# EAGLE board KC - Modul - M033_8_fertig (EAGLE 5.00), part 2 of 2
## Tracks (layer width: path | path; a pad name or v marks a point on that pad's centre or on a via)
80H  (via drill 0.2 pad 0.7)
  Top 0.375: v46.99,58.42 v46.99,71.12 | IC10.3 IC10.12
  Bottom 0.375: IC18.1 12.07,48.26 12.07,58.42 v46.99,58.42 | v46.99,71.12 46.99,73.02 55.88,73.02 IC10.3
/A0  (via drill 0.2 pad 0.7)
  Top 0.375: IC2.11 59.69,35.56 IC5.9 | v50.8,35.56 IC7.1
  Bottom 0.375: v50.8,35.56 59.69,35.56 IC5.9
/A1  (via drill 0.2 pad 0.7)
  Top 0.375: v53.34,40.64 IC7.2 | IC1.11 93.98,34.29 IC4.9
  Bottom 0.375: v53.34,40.64 72.39,40.64 73.66,39.37 91.44,39.37 92.71,40.64 93.98,39.37 IC4.9
/A2
  Top 0.375: IC2.12 57.15,35.56 IC5.8 57.15,39.37 55.88,39.37 IC7.3
/A3  (via drill 0.2 pad 0.7)
  Top 0.375: v91.44,46.99 90.17,45.72 90.17,41.27 88.9,41.27 IC4.8 91.44,34.29 IC1.12
  Bottom 0.375: IC7.4 59.69,46.99 v91.44,46.99
/A4  (via drill 0.2 pad 0.7)
  Top 0.375: IC2.13 54.61,35.56 IC5.7 | v60.96,35.56 IC7.5
  Bottom 0.375: v60.96,35.56 60.96,34.61 57.15,34.61 IC2.13
/A5  (via drill 0.2 pad 0.7)
  Top 0.375: v86.36,40.64 IC4.7 | v63.5,43.18 IC7.6
  Top 0.4: IC4.7 88.9,34.29 IC1.13
  Bottom 0.375: v86.36,40.64 73.66,40.64 72.39,41.91 69.85,41.91 68.58,43.18 v63.5,43.18
/A6  (via drill 0.2 pad 0.7)
  Top 0.375: IC2.14 52.07,35.56 IC5.6 52.07,39.37 54.61,39.37 v54.61,41.91 | IC7.11 58.42,50.8 59.69,50.8 59.69,46.99 58.42,45.72 v58.42,41.91
  Bottom 0.375: v54.61,41.91 v58.42,41.91
/A8  (via drill 0.2 pad 0.7)
  Top 0.375: IC5.5 49.53,35.56 IC2.15 52.07,30.48 v62.23,30.48 | v34.29,62.23 IC8.5 | v95.25,30.48 95.25,64.77 96.52,66.04 v96.52,68.58 | v72.39,93.98 v72.39,69.85 | v40.64,74.93 v40.64,93.98
  Bottom 0.375: v34.29,62.23 27.62,62.23 27.62,63.5 19.05,63.5 19.05,69.53 34.29,69.53 IC9.5 | v62.23,30.48 64.45,30.48 64.45,32.07 68.9,32.07 68.9,30.48 v95.25,30.48 | v96.52,68.58 95.25,69.85 v72.39,69.85 | v40.64,93.98 v72.39,93.98
  Bottom 0.61: v40.64,74.93 39.37,73.66 34.29,73.66 IC9.5 | v40.64,93.98 v72.39,93.98
/A9  (via drill 0.2 pad 0.7)
  Top 0.375: v101.6,34.29 101.6,54.93 102.87,56.2 v102.87,72.39 | v64.77,74.93 64.77,88.58 62.23,88.58 v62.23,91.44 | v33.02,91.44 33.02,81.28 34.29,80.01 35.56,80.01 35.56,77.47 36.83,76.2 IC9.6 36.83,69.85 35.56,68.58 35.56,66.04 36.83,64.77 IC8.6
  Top 0.4: IC4.5 83.82,34.29 IC1.15
  Bottom 0.375: IC1.15 83.82,34.29 v101.6,34.29 | v102.87,72.39 86.36,72.39 86.36,73.66 82.55,73.66 82.55,74.93 v64.77,74.93 | v33.02,91.44 v62.23,91.44
  Bottom 0.61: v33.02,91.44 v62.23,91.44
/A10
  Top 0.375: IC2.16 46.99,35.56 IC5.4
/A11
  Bottom 0.375: IC1.16 81.28,35.24 78.74,35.24 IC4.4
/A12
  Top 0.375: IC2.17 44.45,35.56 IC5.3
/A13  (via drill 0.2 pad 0.7)
  Top 0.375: IC1.17 78.74,34.29 77.47,34.29 76.2,35.56 IC4.3 76.2,41.27 74.93,41.27 v74.93,49.53 | IC21.1 v50.8,62.23 | v66.04,62.23 67.31,60.96 67.31,57.15 68.58,55.88 v68.58,50.8
  Bottom 0.375: v50.8,62.23 v66.04,62.23 | v68.58,50.8 69.85,49.53 v74.93,49.53
/A14  (via drill 0.2 pad 0.7)
  Top 0.375: v38.1,34.29 38.1,39.69 41.91,39.69 IC5.2
  Bottom 0.375: IC2.18 44.45,34.29 v38.1,34.29
/A15
  Top 0.375: IC1.18 76.2,34.29 IC4.2
A0  (via drill 0.2 pad 0.7)
  Top 0.375: IC17.12 52.07,104.14 53.34,102.87 53.34,100.33 52.07,99.06 IC16.12 v52.07,83.82 | IC5.11 v62.23,83.82
  Bottom 0.375: v62.23,83.82 v52.07,83.82
  Bottom 0.61: v52.07,83.82 v62.23,83.82
A1  (via drill 0.2 pad 0.7)
  Top 0.375: v106.68,113.03 107.95,113.03 107.95,96.52 110.49,96.52 110.49,80.01 v111.76,78.74 | v50.8,114.3 50.8,111.76 49.53,110.49 IC17.11 49.53,104.14 50.8,102.87 50.8,100.33 49.53,99.06 IC16.11
  Bottom 0.254: 70.17,112.71 72.07,112.71 | 73.98,112.71 75.88,112.71 | 77.79,112.71 79.69,112.71 | 81.6,112.71 83.5,112.71 | 85.41,112.71 87.31,112.71 | 89.22,112.71 91.12,112.71 | 93.03,112.71 94.93,112.71 | 99.38,112.71 101.28,112.71 | 101.92,112.71 103.82,112.71
  Bottom 0.61: v111.76,78.74 111.76,44.45 IC4.11 | 70.17,112.71 66.36,112.71 66.36,114.3 v50.8,114.3 | 72.07,112.71 73.98,112.71 | 75.88,112.71 77.79,112.71 | 79.69,112.71 81.6,112.71 | 83.5,112.71 85.41,112.71 | 87.31,112.71 89.22,112.71 | 91.12,112.71 93.03,112.71 | 94.93,112.71 99.38,112.71 | 101.28,112.71 101.92,112.71 | 103.82,112.71 106.36,112.71 v106.68,113.03
A2  (via drill 0.2 pad 0.7)
  Top 0.375: IC17.10 46.99,104.14 48.26,102.87 48.26,100.33 46.99,99.06 IC16.10 46.99,73.66 45.72,73.66 v45.72,41.91
  Bottom 0.375: IC5.12 59.69,42.86 51.75,42.86 51.75,41.91 v45.72,41.91
A3  (via drill 0.2 pad 0.7)
  Top 0.375: v90.17,91.44 90.17,93.98 85.09,93.98 85.09,110.49 81.28,110.49 v81.28,118.11 | v45.72,118.11 45.72,115.57 44.45,114.3 IC17.9 44.45,104.14 45.72,102.87 45.72,100.33 44.45,99.06 IC16.9 | v107.95,91.44 107.95,80.01 110.49,77.47 v110.49,45.72
  Bottom 0.254: 79.06,117.79 80.96,117.79 | 73.98,117.79 75.88,117.79 | 69.22,117.79 70.8,117.79 | 90.49,91.76 92.39,91.76 | 93.03,91.76 94.93,91.76 | 95.57,91.76 97.47,91.76
  Bottom 0.375: 95.25,45.72 92.71,45.72 IC4.12
  Bottom 0.61: 80.96,117.79 v81.28,118.11 | 75.88,117.79 79.06,117.79 | 70.8,117.79 73.98,117.79 | 69.22,117.79 46.04,117.79 v45.72,118.11 | 95.25,45.72 v110.49,45.72 | v90.17,91.44 90.49,91.76 | 92.39,91.76 93.03,91.76 | 94.93,91.76 95.57,91.76 | 97.47,91.76 107.63,91.76 v107.95,91.44
A4  (via drill 0.2 pad 0.7)
  Top 0.375: IC17.8 41.91,104.14 43.18,102.87 43.18,100.33 41.91,99.06 IC16.8 41.91,74.93 43.18,73.66 v43.18,46.99 | v57.15,46.99 IC5.13
  Bottom 0.375: v43.18,46.99 v57.15,46.99
A5  (via drill 0.2 pad 0.7)
  Top 0.375: IC16.7 39.37,99.06 40.64,100.33 40.64,102.87 39.37,104.14 IC17.7 | IC4.13 88.9,53.34 83.82,53.34 83.82,57.15 81.28,57.15 v81.28,62.23 | v67.31,62.23 67.31,99.06 68.58,100.33 v68.58,104.14
  Bottom 0.375: v67.31,62.23 v81.28,62.23 | v68.58,104.14 39.37,104.14 IC17.7
  Bottom 0.61: v67.31,62.23 v81.28,62.23
A6  (via drill 0.2 pad 0.7)
  Top 0.375: v96.52,111.76 96.52,113.03 105.41,113.03 105.41,78.74 107.95,76.2 v107.95,46.99 | v36.83,111.76 IC17.6 36.83,104.14 38.1,102.87 38.1,100.33 36.83,99.06 IC16.6
  Bottom 0.254: 65.09,111.76 66.99,111.76
  Bottom 0.375: 99.06,46.99 92.71,46.99 91.44,45.72 54.61,45.72 IC5.14
  Bottom 0.61: v96.52,111.76 66.99,111.76 | 99.06,46.99 v107.95,46.99 | v36.83,111.76 65.09,111.76
A7  (via drill 0.2 pad 0.7)
  Top 0.375: IC16.5 34.29,99.06 35.56,100.33 35.56,102.87 34.29,104.14 IC17.5 | v86.36,52.07 IC4.14 | v38.1,69.85 v38.1,85.09 | v52.07,69.85 52.07,63.5 54.61,63.5 54.61,57.78 55.88,57.78 IC7.12
  Bottom 0.375: 73.66,52.07 73.66,54.61 55.88,54.61 IC7.12 | IC16.5 34.29,85.09 v38.1,85.09 | v38.1,69.85 v52.07,69.85
  Bottom 0.61: 73.66,52.07 v86.36,52.07
A8  (via drill 0.2 pad 0.7)
  Top 0.375: IC17.27 36.83,115.57 35.56,114.3 35.56,104.14 36.83,102.87 IC16.27 36.83,100.33 35.56,99.06 v35.56,81.28 | v52.07,60.96 IC5.15 | v21.59,60.96 21.59,64.77 20.32,66.04 v20.32,81.28
  Bottom 0.375: v52.07,60.96 50.8,60.96 49.53,62.23 38.1,62.23 38.1,60.96 v21.59,60.96 | v20.32,81.28 v35.56,81.28
  Bottom 0.61: v20.32,81.28 v35.56,81.28
A9  (via drill 0.2 pad 0.7)
  Top 0.375: IC16.26 39.37,102.87 38.1,104.14 38.1,114.3 v39.37,115.57 IC17.26 | v105.41,43.18 v105.41,72.39 | v95.25,86.36 v95.25,106.68 | v68.58,105.41 v68.58,115.57
  Bottom 0.375: IC4.15 83.82,43.18 v105.41,43.18 | 95.57,86.36 v95.25,86.36 | v68.58,115.57 v39.37,115.57
  Bottom 0.61: v39.37,115.57 v68.58,115.57 | v68.58,105.41 69.85,106.68 v95.25,106.68 | 95.57,86.36 105.41,86.36 v105.41,72.39
A10  (via drill 0.2 pad 0.7)
  Top 0.375: IC17.23 46.99,115.57 45.72,114.3 45.72,104.14 46.99,102.87 IC16.23 46.99,100.33 45.72,99.06 v45.72,80.01 | v5.08,45.72 5.08,78.74 v6.35,78.74
  Bottom 0.375: IC5.16 49.53,45.72 v5.08,45.72 | 21.59,80.01 v45.72,80.01
  Bottom 0.61: v6.35,78.74 17.46,78.74 17.46,80.01 21.59,80.01
A11  (via drill 0.2 pad 0.7)
  Top 0.375: IC17.25 41.91,115.57 40.64,114.3 40.64,104.14 41.91,102.87 IC16.25 41.91,100.33 40.64,99.06 v40.64,96.52 | IC4.16 81.28,52.07 73.66,52.07 v73.66,81.28 | v55.88,81.28 v55.88,96.52
  Bottom 0.375: v73.66,81.28 v55.88,81.28 | v55.88,96.52 v40.64,96.52
  Bottom 0.61: v40.64,96.52 v55.88,96.52 | v55.88,81.28 v73.66,81.28
A12  (via drill 0.2 pad 0.7)
  Top 0.375: IC17.4 31.75,104.14 33.02,102.87 33.02,100.33 31.75,99.06 IC16.4 31.75,81.28 33.02,80.01 33.02,57.78 35.56,57.78 v35.56,43.18
  Bottom 0.375: IC5.17 46.99,43.18 v35.56,43.18
A13  (via drill 0.2 pad 0.7)
  Top 0.375: IC21.4 58.42,57.78 59.69,57.78 v59.69,53.34 | v78.74,50.8 IC4.17
  Bottom 0.375: v59.69,53.34 68.58,53.34 69.85,52.07 71.12,52.07 72.39,50.8 v78.74,50.8
AB0  (via drill 0.2 pad 0.7)
  Top 0.375: v59.69,11.43 IC2.9
  Bottom 0.375: 67.31,4.45 PAD110.1 PAD81.1
  Bottom 0.61: v59.69,11.43 63.5,11.43 67.31,7.62 67.31,4.45
AB1  (via drill 0.2 pad 0.7)
  Top 0.375: v91.44,12.7 IC1.9 | v76.2,7.62 v76.2,12.7 | v68.58,6.35 67.31,6.35 PAD52.1 PAD23.1
  Bottom 0.375: v76.2,12.7 v91.44,12.7
  Bottom 0.61: v76.2,12.7 v91.44,12.7 | v68.58,6.35 68.58,7.62 v76.2,7.62
AB2  (via drill 0.2 pad 0.7)
  Top 0.375: v57.15,11.43 IC2.8
  Bottom 0.375: 64.77,4.76 PAD109.1 PAD80.1
  Bottom 0.61: 64.77,4.76 64.77,8.89 63.18,10.48 58.1,10.48 v57.15,11.43
AB3  (via drill 0.2 pad 0.7)
  Top 0.375: v88.9,13.97 IC1.8 | v66.04,12.7 66.04,7.62 64.77,7.62 PAD51.1 PAD22.1
  Bottom 0.61: v66.04,12.7 73.66,12.7 73.66,13.97 v88.9,13.97
AB4  (via drill 0.2 pad 0.7)
  Top 0.375: IC2.7 54.61,21.59 53.34,21.59 v53.34,10.16
  Bottom 0.375: 62.23,4.45 PAD108.1 PAD79.1
  Bottom 0.61: v53.34,10.16 53.98,9.53 62.23,9.53 62.23,4.45
AB5  (via drill 0.2 pad 0.7)
  Top 0.375: v86.36,19.05 IC1.7 | v64.77,19.05 64.77,8.89 62.23,8.89 PAD50.1 PAD21.1
  Bottom 0.375: v64.77,19.05 v86.36,19.05
AB6  (via drill 0.2 pad 0.7)
  Top 0.375: v52.07,8.89 IC2.6
  Bottom 0.375: 59.69,4.45 PAD107.1 PAD78.1
  Bottom 0.61: v52.07,8.89 52.39,8.57 59.69,8.57 59.69,4.45
AB7  (via drill 0.2 pad 0.7)
  Top 0.375: v83.82,15.24 IC1.6 | v63.5,15.24 63.5,10.16 59.69,10.16 PAD49.1 PAD20.1
  Bottom 0.375: v63.5,15.24 v83.82,15.24
AB8  (via drill 0.2 pad 0.7)
  Top 0.375: IC2.5 49.53,8.89 v50.8,7.62
  Bottom 0.375: 54.61,4.76 PAD105.1 PAD76.1
  Bottom 0.61: v50.8,7.62 54.61,7.62 54.61,4.76
AB9  (via drill 0.2 pad 0.7)
  Top 0.375: v81.28,11.43 IC1.5 | v55.88,12.7 55.88,6.98 54.61,6.98 PAD47.1 PAD18.1
  Bottom 0.61: v55.88,12.7 63.5,12.7 64.77,11.43 v81.28,11.43
AB10  (via drill 0.2 pad 0.7)
  Top 0.375: IC2.4 46.99,27.94 50.8,27.94 v50.8,11.43 | v50.8,6.35 v48.26,8.89
  Bottom 0.375: 52.07,4.76 PAD104.1 PAD75.1
  Bottom 0.61: v50.8,6.35 52.07,6.35 52.07,4.76 | v48.26,8.89 46.99,10.16 46.99,11.43 v50.8,11.43
AB11  (via drill 0.2 pad 0.7)
  Top 0.375: v60.96,19.05 v60.96,22.86 | v54.61,19.05 54.61,7.94 52.07,7.94 PAD46.1 PAD17.1
  Bottom 0.375: IC1.4 78.74,22.86 v60.96,22.86
  Bottom 0.4: v54.61,19.05 55.25,18.42 60.33,18.42 v60.96,19.05
AB12  (via drill 0.2 pad 0.7)
  Top 0.375: IC2.3 44.45,18.73 48.26,18.73 v48.26,10.16
  Bottom 0.375: 49.53,4.45 PAD103.1 PAD74.1
  Bottom 0.61: v48.26,10.16 49.53,10.16 49.53,4.45
AB13  (via drill 0.2 pad 0.7)
  Top 0.375: v76.2,17.78 IC1.3 | v46.99,17.78 46.99,7.62 48.26,6.35 49.53,6.35 PAD45.1 PAD16.1
  Bottom 0.375: v46.99,17.78 v76.2,17.78
AB14  (via drill 0.2 pad 0.7)
  Top 0.375: v41.91,10.16 IC2.2
  Bottom 0.375: 46.99,4.76 PAD102.1 PAD73.1
  Bottom 0.61: v41.91,10.16 45.72,10.16 46.99,8.89 46.99,4.76
AB15  (via drill 0.2 pad 0.7)
  Top 0.375: IC1.2 73.66,22.86 71.12,22.86 v71.12,13.97 | v45.72,12.7 45.72,7.62 46.99,6.35 PAD44.1 PAD15.1
  Bottom 0.61: v45.72,12.7 48.26,12.7 49.53,13.97 v71.12,13.97
B_03A
  Bottom 0.375: PAD94.1 PAD65.1
B_03B
  Top 0.375: PAD36.1 PAD7.1
B_08A  (via drill 0.2 pad 0.7)
  Top 0.375: IC3.2 10.16,35.56 11.43,34.29 v11.43,27.94 | v35.56,27.94 35.56,16.51 36.83,16.51 36.83,8.89 v39.37,6.35
  Bottom 0.375: v35.56,27.94 v11.43,27.94 | 39.37,5.08 PAD99.1 PAD70.1
  Bottom 0.61: v35.56,27.94 v11.43,27.94
  Bottom 0.7: v39.37,6.35 39.37,5.08
B_08B  (via drill 0.2 pad 0.7)
  Top 0.375: v19.05,15.24 19.05,13.97 10.16,13.97 10.16,21.59 11.43,21.59 11.43,26.99 13.97,26.99 13.97,34.29 15.24,35.56 IC3.4 | PAD12.1 PAD41.1 39.37,5.08 35.56,8.89 v35.56,13.97
  Bottom 0.375: 28.89,14.6 29.53,13.97 v35.56,13.97
  Bottom 0.4: 28.89,14.6 19.69,14.6 v19.05,15.24
B_09A  (via drill 0.2 pad 0.7)
  Top 0.375: v43.18,8.89 v43.18,35.56
  Bottom 0.375: IC3.3 12.7,35.56 v43.18,35.56 | 41.91,4.76 PAD100.1 PAD71.1
  Bottom 0.61: v43.18,8.89 41.91,8.89 41.91,4.76
B_09B  (via drill 0.2 pad 0.7)
  Top 0.375: IC3.5 v17.78,39.37 | v24.13,30.48 v24.13,19.05 | v39.37,19.05 39.37,8.89 41.91,6.35 PAD42.1 PAD13.1
  Bottom 0.375: v17.78,39.37 3.81,39.37 3.81,31.43 15.56,31.43 16.51,30.48 v24.13,30.48 | v24.13,19.05 v39.37,19.05
B_10A
  Bottom 0.375: PAD101.1 PAD72.1
B_15A
  Bottom 0.375: PAD77.1 PAD106.1
B_15B  (via drill 0.2 pad 0.7)
  Top 0.375: IC3.6 v20.32,39.37 | v44.45,40.64 45.72,40.64 v45.72,35.56 | v50.8,31.75 50.8,28.89 53.34,28.89 v53.34,22.86 | v58.42,22.86 58.42,8.57 57.15,8.57 PAD48.1 PAD19.1
  Bottom 0.375: v20.32,39.37 24.77,39.37 24.77,40.64 v44.45,40.64 | v45.72,35.56 45.72,34.61 50.8,34.61 v50.8,31.75 | v53.34,22.86 v58.42,22.86
  Bottom 0.61: v53.34,22.86 v58.42,22.86
B_20A
  Bottom 0.375: PAD82.1 PAD111.1
B_20B  (via drill 0.2 pad 0.7)
  Top 0.375: v63.5,19.05 64.77,20.32 67.31,20.32 v67.31,10.16 | v69.85,8.89 PAD53.1 PAD24.1 | v45.72,31.75 v45.72,22.86 | v36.83,38.1 v36.83,31.75
  Bottom 0.375: v36.83,31.75 v45.72,31.75 | v36.83,38.1 25.4,38.1 IC3.8
  Bottom 0.4: v63.5,19.05 62.23,19.05 62.23,20.32 59.69,20.32 59.69,21.59 50.8,21.59 50.8,22.86 v45.72,22.86
  Bottom 0.61: v67.31,10.16 67.31,9.21 67.63,8.89 v69.85,8.89
B_21A
  Bottom 0.375: PAD83.1 PAD112.1
B_21B
  Top 0.375: PAD25.1 PAD54.1
B_22A
  Bottom 0.375: PAD84.1 PAD113.1
B_22B
  Top 0.375: PAD26.1 PAD55.1
B_23A
  Bottom 0.375: PAD85.1 PAD114.1
B_23B
  Top 0.375: PAD27.1 PAD56.1
B_25A
  Bottom 0.375: PAD87.1 PAD116.1
B_25B
  Top 0.375: PAD29.1 PAD58.1
B_26A  (via drill 0.2 pad 0.7)
  Top 0.375: IC3.9 v27.94,39.37 | v72.39,39.37 v72.39,43.18
  Bottom 0.375: v27.94,39.37 v72.39,39.37 | v72.39,43.18 73.66,41.91 95.89,41.91 | 85.09,4.45 PAD117.1 PAD88.1
  Bottom 0.61: 95.89,41.91 95.89,39.05 100.33,39.05 100.33,35.56 113.03,35.56 113.03,12.7 93.98,12.7 93.98,11.43 85.09,11.43 85.09,4.45
B_26B
  Top 0.375: PAD30.1 PAD59.1
B_27A
  Bottom 0.375: PAD89.1 PAD118.1
B_27B
  Top 0.375: PAD31.1 PAD60.1
B_28A
  Bottom 0.375: PAD90.1 PAD119.1
B_28B
  Top 0.375: PAD32.1 PAD61.1
CSRAM1  (via drill 0.2 pad 0.7)
  Top 0.375: IC21.3 55.88,64.77 54.61,64.77 v54.61,82.55 | v48.26,82.55 48.26,99.06 49.53,100.33 IC16.22
  Bottom 0.375: v54.61,82.55 v48.26,82.55
  Bottom 0.61: v48.26,82.55 v54.61,82.55
CSRAM2  (via drill 0.2 pad 0.7)
  Top 0.375: v49.53,113.03 IC17.22 | v63.5,91.44 v63.5,113.03 | v69.85,73.66 v69.85,90.17 | v64.77,73.66 64.77,64.77 63.5,64.77 IC21.6
  Bottom 0.254: 64.77,89.85 65.09,89.85 66.99,89.85
  Bottom 0.375: v63.5,113.03 v49.53,113.03 | v63.5,91.44 63.5,90.17 | v64.77,73.66 v69.85,73.66
  Bottom 0.61: v63.5,113.03 v49.53,113.03 | 66.99,89.85 69.53,89.85 v69.85,90.17 | v64.77,73.66 v69.85,73.66 | 65.09,89.85 63.5,89.85 v63.5,91.44
D0  (via drill 0.2 pad 0.7)
  Top 0.375: v6.35,95.25 6.35,86.36 2.54,86.36 v2.54,52.07 | PAD11.1 PAD40.1 36.83,6.35 33.02,10.16 33.02,16.51 R1.1 | v26.67,16.51 v26.67,12.7 | IC17.13 54.61,104.14 55.88,102.87 55.88,100.33 54.61,99.06 v54.61,97.79 v54.61,88.9 IC16.13 | S1.8 77.47,97.79 v77.47,88.9
  Bottom 0.375: R1.1 v26.67,16.51 | v54.61,88.9 v77.47,88.9
  Bottom 0.61: v2.54,52.07 1.27,52.07 1.27,12.7 v26.67,12.7 | v54.61,88.9 v77.47,88.9 | v54.61,97.79 32.39,97.79 32.39,96.52 9.84,96.52 9.84,95.25 v6.35,95.25
D1  (via drill 0.2 pad 0.7)
  Top 0.375: v5.08,34.29 v5.08,44.45 | v34.29,10.16 34.29,20.32 R2.1 v31.75,31.75 | IC17.14 57.15,104.14 58.42,102.87 58.42,100.33 v57.15,99.06 IC16.14
  Bottom 0.254: 50.8,100.65 50.8,103.19 38.42,103.19 | 53.02,100.01 51.12,100.01 | 54.93,100.01 53.66,100.01
  Bottom 0.375: PAD69.1 PAD98.1 36.83,4.76 36.83,5.08 | v5.08,34.29 16.51,34.29 16.51,31.75 v31.75,31.75
  Bottom 0.406: 36.83,7.62 36.83,5.08
  Bottom 0.61: 36.83,4.76 36.83,7.62 38.1,7.62 39.37,8.89 39.37,10.16 v34.29,10.16 | v5.08,44.45 3.49,44.45 3.49,47.31 7.94,47.31 8.89,48.26 10.16,48.26 10.16,54.93 3.81,54.93 3.81,63.5 0.64,63.5 0.64,96.52 6.35,96.52 6.35,103.19 23.18,103.19 23.5,103.5 38.1,103.5 38.42,103.19 | 50.8,100.65 50.8,100.01 51.12,100.01 | 53.66,100.01 53.02,100.01 | 77.47,99.38 77.15,99.38 76.84,99.06 v57.15,99.06 55.88,99.06 54.93,100.01
D2  (via drill 0.2 pad 0.7)
  Top 0.375: v104.14,96.52 104.14,78.74 106.68,76.2 v106.68,27.94 | v69.85,16.51 v69.85,27.94 | PAD10.1 PAD39.1 34.29,7.62 v33.02,8.89 | v44.45,12.7 v44.45,15.24 | IC17.15 59.69,104.14 60.96,102.87 60.96,100.33 59.69,99.06 v59.69,96.52 IC16.15
  Bottom 0.254: 80.33,96.2 82.23,96.2 | 79.69,96.2 77.79,96.2 77.47,96.2 | 84.14,96.2 85.41,96.2 87.31,96.2 | 87.95,96.2 89.85,96.2 | 90.49,96.2 92.39,96.2 | 93.03,96.2 94.93,96.2 | 95.57,96.2 97.47,96.2
  Bottom 0.375: v69.85,27.94 v106.68,27.94 | v69.85,16.51 R3.1 49.21,16.51 47.94,15.24 | S1.6 83.82,96.52
  Bottom 0.4: 47.94,15.24 47.31,14.6 45.09,14.6 v44.45,15.24
  Bottom 0.61: v69.85,27.94 v106.68,27.94 | v33.02,8.89 31.75,8.89 31.75,12.7 v44.45,12.7 | 83.82,96.2 84.14,96.2 | 83.82,96.2 S1.6 | 82.23,96.2 83.82,96.2 | 79.69,96.2 80.33,96.2 | 77.79,96.2 60.01,96.2 v59.69,96.52 | v104.14,96.52 103.82,96.2 97.47,96.2 | 95.57,96.2 94.93,96.2 | 93.03,96.2 92.39,96.2 | 90.49,96.2 89.85,96.2 | 87.95,96.2 87.31,96.2 | 85.41,96.2 83.82,96.2
D3  (via drill 0.2 pad 0.7)
  Top 0.375: IC17.17 62.23,115.57 60.96,114.3 60.96,104.14 62.23,102.87 IC16.17 v62.23,95.25 | v86.36,95.25 S1.5 | v111.76,92.71 113.03,92.71 113.03,31.75 v111.76,31.75 | v64.77,34.29 64.77,27.94 55.88,27.94 R4.1 | v39.37,7.62 v38.1,8.89 | v40.64,8.89 v40.64,19.05
  Bottom 0.375: v86.36,95.25 v62.23,95.25 | 86.68,92.71 86.36,92.71 | v111.76,31.75 80.01,31.75 80.01,34.29 v64.77,34.29 | R4.1 50.8,20.32 50.8,19.05 v40.64,19.05 | v40.64,8.89 v39.37,7.62 | PAD68.1 PAD97.1 34.29,4.76
  Bottom 0.406: v39.37,7.62 v40.64,8.89
  Bottom 0.61: v62.23,95.25 v86.36,95.25 86.36,92.71 87,92.71 | 86.68,92.71 87,92.71 | 87,92.71 v111.76,92.71 | v39.37,7.62 v40.64,8.89 | v38.1,8.89 35.56,8.89 35.56,6.67 34.29,6.67 34.29,4.76
D4  (via drill 0.2 pad 0.7)
  Top 0.375: v87.63,120.65 88.9,120.65 S1.4 v88.9,95.25 | v102.87,95.25 102.87,78.74 104.14,77.47 v104.14,13.97 | PAD9.1 PAD38.1 31.75,12.7 30.48,12.7 v30.48,15.24 | v62.23,15.24 v62.23,21.59 | IC17.18 59.69,115.57 58.42,114.3 58.42,104.14 59.69,102.87 IC16.18
  Bottom 0.254: 68.9,120.65 70.8,120.65 | 73.98,120.65 75.88,120.65 | 79.06,120.65 80.96,120.65 | 84.14,120.65 86.04,120.65
  Bottom 0.375: v102.87,95.25 v88.9,95.25 | 93.98,13.97 v104.14,13.97 111.76,13.97 | v62.23,21.59 80.01,21.59 | v62.23,15.24 49.53,15.24 48.26,13.97 39.05,13.97 38.1,14.92
  Bottom 0.4: v30.48,15.24 31.12,14.6 33.97,14.6 34.29,14.92 38.1,14.92
  Bottom 0.61: 68.9,120.65 65.72,120.65 65.72,118.75 59.69,118.75 IC17.18 | 70.8,120.65 73.98,120.65 | 75.88,120.65 79.06,120.65 | 80.96,120.65 84.14,120.65 | 86.04,120.65 v87.63,120.65 | v88.9,95.25 v102.87,95.25 | R5.1 93.98,16.51 93.98,13.97 111.76,13.97 111.76,22.86 80.01,22.86 80.01,21.59
D5  (via drill 0.2 pad 0.7)
  Top 0.375: v91.44,107.95 S1.3 v91.44,93.98 | v109.22,93.98 109.22,80.01 111.76,77.47 111.76,39.05 110.49,39.05 v110.49,21.59 | v82.55,26.67 R6.1 | v36.83,27.94 36.83,24.13 38.1,22.86 v38.1,11.43 | IC17.19 57.15,107.95 v55.88,106.68 55.88,104.14 57.15,102.87 IC16.19
  Bottom 0.254: 66.99,107 65.09,107 | 63.18,107 61.28,107 | 60.64,107 58.74,107 | 58.1,107 56.2,107
  Bottom 0.375: v109.22,93.98 v91.44,93.98 | PAD67.1 PAD96.1 31.75,4.76 | v82.55,26.67 68.26,26.67 68.26,27.94 v36.83,27.94
  Bottom 0.61: v91.44,107.95 69.53,107.95 68.58,107 66.99,107 | v109.22,93.98 v91.44,93.98 | v110.49,21.59 93.98,21.59 93.98,20.32 R6.1 | 31.75,4.76 31.75,7.62 34.29,7.62 34.29,8.89 33.02,10.16 33.02,11.43 v38.1,11.43 | 65.09,107 63.18,107 | 61.28,107 60.64,107 | 58.74,107 58.1,107 | 56.2,107 v55.88,106.68
D6  (via drill 0.2 pad 0.7)
  Top 0.375: IC17.20 54.61,111.76 53.34,110.49 53.34,104.14 54.61,102.87 IC16.20 54.61,100.33 53.34,99.06 v53.34,95.25 | PAD8.1 PAD37.1 29.21,46.35 27.94,46.35 v27.94,53.34 | v19.05,53.34 v19.05,95.25
  Bottom 0.254: 63.18,100.01 61.28,100.01 | 60.64,100.01 58.74,100.01 | 58.1,100.01 56.2,100.01 55.88,100.33
  Bottom 0.375: IC16.20 55.88,100.33 | v27.94,53.34 v19.05,53.34 R7.1
  Bottom 0.61: R7.1 v27.94,53.34 | S1.2 93.98,100.33 63.5,100.33 63.18,100.01 | 61.28,100.01 60.64,100.01 | 58.74,100.01 58.1,100.01 | 56.2,100.01 IC16.20 | v53.34,95.25 32.39,95.25 v19.05,95.25
D7  (via drill 0.2 pad 0.7)
  Top 0.375: v5.08,90.17 1.27,90.17 1.27,29.21 3.81,29.21 | 3.81,29.21 v3.81,13.97 | R8.1 3.81,29.21 | IC17.21 52.07,111.76 50.8,110.49 50.8,104.14 52.07,102.87 IC16.21 52.07,100.33 50.8,99.06 v50.8,90.17 | v96.52,102.87 S1.1
  Bottom 0.254: 13.02,90.8 14.92,90.8
  Bottom 0.375: PAD66.1 PAD95.1 29.21,13.02 28.26,13.97 v3.81,13.97 | v96.52,102.87 52.07,102.87 IC16.21
  Bottom 0.61: v5.08,90.17 10.48,90.17 10.48,90.8 13.02,90.8 | 14.92,90.8 16.83,90.8 16.83,90.17 v50.8,90.17
GND  (via drill 0.2 pad 0.7)
  Top 0.375: C5.1 99.06,25.4 99.06,36.83 | v100.33,71.12 100.33,59.69 99.06,59.69 | 99.06,59.69 C15.1 | 99.06,36.83 C13.1 | C8.1 71.12,68.58 72.39,67.31 72.39,62.23 71.12,60.96 C4.1 71.12,57.15 72.39,55.88 72.39,48.26 | 99.06,48.26 99.06,36.83 | 99.06,48.26 99.06,59.69 | C6.1 99.06,48.26 | 72.39,48.26 C7.1 | IC1.19 73.66,30.8 72.39,30.8 | IC1.1 71.12,30.8 72.39,30.8 | 72.39,48.26 73.66,48.26 IC4.19 73.66,38.42 71.12,38.42 IC4.1 71.12,34.92 72.39,34.92 72.39,30.8 | S2.1 7.62,48.26 10.16,48.26 IC3.19 v10.16,40.64 | PAD6.1 PAD35.1 24.13,4.45 | PAD5.1 PAD34.1 21.59,4.76 | v7.62,40.64 IC3.1 7.62,35.56 8.89,34.29 8.89,26.99 7.62,26.99 IC11.1 | IC5.1 39.37,35.56 IC2.19 41.91,27.94 39.37,27.94 IC2.1 | C17.1 66.04,100.33 64.77,99.06 64.77,89.53 66.04,89.53 C16.1 | v73.66,86.36 73.66,121.92 D7.K | D1.K 100.33,121.92 D3.K | IC17.24 44.45,115.57 43.18,114.3 43.18,104.14 44.45,102.87 IC16.24 44.45,100.33 43.18,99.06 43.18,74.93 44.45,73.66 C1.1 | IC9.7 39.37,73.66 41.28,73.66 41.91,73.02 41.91,66.04 40.64,64.77 39.37,64.77 IC8.7 40.64,59.69 40.64,54.61 39.37,53.34 IC18.7 | C14.1 44.45,46.04 41.91,46.04 IC5.19
  Top 0.4: v43.18,38.1 43.18,41.91 41.91,41.91 IC5.19
  Top 1: 24.13,4.45 v24.13,6.35 21.59,6.35 | 21.59,6.35 21.59,4.76 | 21.59,6.35 21.59,12.7 7.62,12.7 IC11.1
  Bottom 0.375: IC12.7 C19.1 v100.33,71.12 | C5.1 IC1.10 | C13.1 IC4.10 | C15.1 IC13.7 | C8.1 IC10.7 | C6.1 IC19.7 92.71,49.85 75.88,49.85 75.88,48.26 C7.1 IC7.7 | C4.1 IC21.7 | IC2.10 C3.1 IC1.1 | 21.59,2.54 PAD34.1 | 21.59,2.54 PAD5.1 | 24.13,2.54 21.59,2.54 | 24.13,2.54 PAD6.1 | IC4.1 C9.1 IC5.10 62.23,38.1 v43.18,38.1 39.37,38.1 IC5.1 C11.1 IC3.10 | v7.62,40.64 v10.16,40.64 | 24.13,2.54 PAD35.1 24.13,4.76 | IC11.1 7.62,21.59 24.13,21.59 24.13,20.32 30.16,20.32 30.16,21.91 39.37,21.91 IC2.1 C18.1 IC11.10 | C17.1 IC17.16 | IC16.16 C16.1 v73.66,86.36 | D3.K D4.K D5.K D6.K D7.K D8.K | IC17.24 44.45,121.92 | IC9.7 C1.1 | C14.1 IC18.7
  Bottom 0.61: v10.16,40.64 v7.62,40.64
  Bottom 0.65: v100.33,71.12 C19.1 | v73.66,86.36 C16.1
  Bottom 0.7: v24.13,6.35 24.13,4.76
  Bottom 1: C19.1 IC12.7 | C5.1 IC1.10 | C13.1 IC4.10 | C15.1 IC13.7 | C8.1 IC10.7 | IC19.7 C6.1 | C4.1 IC21.7 | C7.1 IC7.7 | IC1.1 IC2.10 | IC5.10 IC4.1 | IC3.10 C11.1 IC5.1 | C17.1 IC17.16 | C16.1 IC16.16 | D3.K D8.K 69.22,122.55 44.45,122.55 | D2.K 10.8,122.55 44.45,122.55 | IC17.24 44.45,122.55 | IC9.7 C1.1 | IC8.7 C10.1 | C14.1 IC18.7
IC13  (via drill 0.2 pad 0.7)
  Top 0.375: IC16.28 34.29,102.87 33.02,104.14 v33.02,109.22 33.02,114.3 34.29,115.57 IC17.28 | v19.05,118.11 19.05,104.14 17.78,104.14 v17.78,72.39 | v13.97,57.15 v13.97,71.12 | v15.24,50.8 v15.24,55.88 | v22.86,50.8 22.86,46.35 24.13,46.35 24.13,31.75 20.32,27.94 IC11.6 | v90.17,110.49 R11.2
  Bottom 0.254: 67.31,108.9 65.09,108.9
  Bottom 0.375: v17.78,72.39 15.24,72.39 v13.97,71.12 | v15.24,55.88 v13.97,57.15 | v22.86,50.8 v15.24,50.8
  Bottom 0.61: IC17.28 34.29,118.11 v19.05,118.11 | v15.24,55.88 v13.97,57.15 | v22.86,50.8 v15.24,50.8 | v90.17,110.49 68.9,110.49 67.31,108.9 | 65.09,108.9 33.34,108.9 v33.02,109.22
IC16  (via drill 0.2 pad 0.7)
  Top 0.375: R14.2 77.47,104.14 v77.47,115.57 | IC17.2 v26.67,116.84 26.67,118.11 27.94,119.38 27.94,122.55 21.59,122.55 v21.59,85.09 21.59,66.04 22.86,64.77 v22.86,62.23 | v11.43,62.23 11.43,58.1 10.16,58.1 10.16,49.53 v8.89,49.53 | v11.43,38.1 v11.43,40.64 | v21.59,38.1 21.59,35.56 20.32,34.29 IC11.15
  Bottom 0.254: 25.08,84.77 23.18,84.77
  Bottom 0.375: v11.43,62.23 v22.86,62.23 | v8.89,49.53 7.62,48.26 2.54,48.26 2.54,41.91 10.16,41.91 v11.43,40.64 | v21.59,38.1 v11.43,38.1
  Bottom 0.61: v77.47,115.57 77.47,116.84 v26.67,116.84 | v21.59,85.09 21.91,84.77 23.18,84.77 | 25.08,84.77 25.4,84.77 26.67,86.04 IC16.2
IC17  (via drill 0.2 pad 0.7)
  Top 0.375: IC11.16 17.78,34.29 19.05,35.56 v19.05,52.07 | v25.4,52.07 v25.4,92.71 25.4,97.79 26.67,99.06 27.94,99.06 29.21,100.33 IC16.30 29.21,102.87 27.94,104.14 27.94,114.3 29.21,115.57 IC17.30 | v74.93,92.71 R15.2
  Bottom 0.375: v19.05,52.07 v25.4,52.07 | v25.4,92.71 v74.93,92.71
  Bottom 0.61: v25.4,52.07 v19.05,52.07 | v25.4,92.71 v74.93,92.71
IC_A_14  (via drill 0.2 pad 0.7)
  Top 0.375: v101.6,80.01 v101.6,102.87 | v59.69,77.47 59.69,83.82 58.42,85.09 v58.42,87.63 | S3.2 10.16,72.07 11.43,70.8 11.43,65.41 12.7,65.41 S2.3 12.7,57.15 11.43,57.15 v11.43,41.91 | v31.75,34.29 v31.75,41.91 | v26.67,34.29 26.67,30.48 27.94,29.21 IC11.9
  Bottom 0.254: 89.22,105.73 91.12,105.73 | 93.03,105.73 94.93,105.73
  Bottom 0.375: 96.52,77.47 99.06,77.47 | v59.69,77.47 74.3,77.47 | v58.42,87.63 50.8,87.63 49.53,88.9 | 11.43,69.85 11.43,67.31 | v31.75,41.91 v11.43,41.91 | v26.67,34.29 v31.75,34.29
  Bottom 0.61: v101.6,80.01 103.19,80.01 103.19,77.47 99.06,77.47 | 96.52,77.47 95.25,77.47 93.98,76.2 74.3,76.2 74.3,77.47 | 11.43,67.31 11.43,65.72 3.49,65.72 3.49,87 16.51,87 16.51,88.9 49.53,88.9 | 11.43,69.85 11.43,72.39 S3.2 | v31.75,41.91 v11.43,41.91 | 89.22,105.73 86.36,105.73 R12.2 | 94.93,105.73 96.2,105.73 99.06,102.87 v101.6,102.87 | 93.03,105.73 91.12,105.73
IC_A_15  (via drill 0.2 pad 0.7)
  Top 0.375: v16.51,63.5 16.51,71.12 15.24,72.39 S3.4 | v27.94,30.48 IC11.12 | v6.35,29.21 v6.35,63.5 | R13.2 82.55,86.36 83.82,86.36 v83.82,82.55
  Bottom 0.375: v83.82,82.55 81.28,82.55 81.28,81.28 | 75.25,80.01 48.26,80.01 48.26,78.11 41.91,78.11 41.91,76.2
  Bottom 0.61: 75.25,80.01 75.25,81.28 81.28,81.28 | v27.94,30.48 25.4,30.48 25.4,29.21 v6.35,29.21 | v6.35,63.5 10.16,63.5 | 10.16,63.5 v16.51,63.5 | 10.16,63.5 S2.2 | 41.91,76.2 38.1,76.2 38.1,74.93 15.24,74.93 S3.4
IC_A_18  (via drill 0.2 pad 0.7)
  Top 0.375: IC11.19 10.16,34.29 8.89,35.56 v8.89,46.99 | v12.7,46.99 12.7,54.61 15.24,57.15 S2.4 | v8.89,55.88 8.89,71.12 7.62,72.39 S3.1 7.62,74.93 8.89,76.2 v8.89,113.03 | R16.2 72.39,104.14 72.39,120.65 65.09,120.65 65.09,116.84 62.23,113.98 v62.23,110.49
  Bottom 0.375: 11.11,46.99 v12.7,46.99 | v8.89,46.99 11.11,46.99 | 11.11,46.99 11.11,47.31
  Bottom 0.61: v8.89,55.88 11.11,55.88 11.11,47.31 | v8.89,46.99 v12.7,46.99 | v62.23,110.49 20.32,110.49 20.32,113.03 v8.89,113.03
IC_WE  (via drill 0.2 pad 0.7)
  Top 0.375: S3.3 12.7,74.93 13.97,76.2 13.97,85.09 11.43,85.09 v11.43,88.9
  Bottom 0.375: v11.43,88.9 R17.2
  Bottom 0.61: R17.2 v11.43,88.9
IE_I_O
  Top 0.375: PAD43.1 PAD14.1
IORQ  (via drill 0.2 pad 0.7)
  Top 0.375: IC3.15 v20.32,64.77 | IC9.11 31.75,73.66 30.48,72.39 30.48,69.85 31.75,68.58 IC8.11
  Bottom 0.375: v20.32,64.77 20.32,68.9 25.4,68.9 25.4,65.41 31.75,65.41 IC8.11
LATCH  (via drill 0.2 pad 0.7)
  Top 0.375: v63.5,29.21 63.5,41.91 64.77,41.91 v64.77,57.15 | v101.6,58.42 v101.6,78.74 | v71.12,78.74 v71.12,82.55 | v58.42,82.55 IC10.11
  Bottom 0.375: IC11.11 35.88,33.02 35.88,29.21 v63.5,29.21 | v64.77,57.15 81.28,57.15 81.28,58.42 v101.6,58.42 | 93.98,77.47 75.25,77.47 | v71.12,82.55 v58.42,82.55
  Bottom 0.61: v101.6,78.74 95.25,78.74 93.98,77.47 | 75.25,77.47 75.25,78.74 v71.12,78.74 | v58.42,82.55 v71.12,82.55
MAD  (via drill 0.2 pad 0.7)
  Top 0.375: v35.56,69.85 v35.56,76.2 | IC3.11 30.48,49.85 32.07,49.85 33.02,50.8 v33.02,54.61 | v27.94,54.61 27.94,60.96 29.21,62.23 IC8.12
  Bottom 0.375: IC8.12 29.21,68.9 34.61,68.9 v35.56,69.85 | v35.56,76.2 29.21,76.2 | v33.02,54.61 v27.94,54.61
  Bottom 0.61: 35.88,76.2 29.21,76.2 IC9.12
MEI  (via drill 0.2 pad 0.7)
  Top 0.375: PAD28.1 PAD57.1 80.01,38.1 85.09,38.1 IC19.4 85.09,52.07 82.55,52.07 82.55,53.34 78.74,53.34 v78.74,58.42 | v38.1,41.91 v38.1,57.15 | v48.26,54.61 v48.26,40.64
  Bottom 0.375: IC19.4 IC19.5 | IC18.13 26.67,57.15 v38.1,57.15 | v38.1,41.91 44.45,41.91 45.72,40.64 v48.26,40.64 | v48.26,54.61 54.61,54.61 54.61,57.47 62.23,57.47 62.23,58.42 v78.74,58.42
  Bottom 0.61: IC19.4 IC19.5
MEO  (via drill 0.2 pad 0.7)
  Top 0.375: v31.75,50.8 IC18.11 | v67.31,50.8 68.58,49.53 v68.58,10.16
  Bottom 0.375: v67.31,50.8 v31.75,50.8 | 80.01,4.76 PAD115.1 PAD86.1
  Bottom 0.61: 80.01,4.76 80.01,10.16 v68.58,10.16
MKA  (via drill 0.2 pad 0.7)
  Top 0.375: IC13.5 IC13.10 IC12.5 IC12.10 | IC12.13 IC12.2 IC13.13 IC13.2 | IC18.3 v29.21,52.07 | v57.15,52.07 v57.15,60.96
  Bottom 0.375: v29.21,52.07 v57.15,52.07 | v57.15,60.96 80.01,60.96 | 80.01,60.96 IC13.2 | IC13.5 87.63,60.96 80.01,60.96
MREQ  (via drill 0.2 pad 0.7)
  Top 0.375: IC3.17 v15.24,46.99 | v33.02,46.99 33.02,49.53 34.29,50.8 IC18.10
  Bottom 0.375: v15.24,46.99 v33.02,46.99
N$1  (via drill 0.2 pad 0.7)
  Top 0.375: v69.85,55.88 68.58,57.15 v68.58,69.85
  Bottom 0.375: IC10.1 IC10.2 53.34,69.85 v68.58,69.85 | v69.85,55.88 IC7.8
  Bottom 0.61: IC7.8 v69.85,55.88 | 53.66,71.12 IC10.1
N$2
  Top 0.375: IC12.1 77.47,72.39 78.74,73.66 78.74,81.28 80.01,81.28 RN1.2
N$3
  Top 0.375: IC12.4 85.09,76.2 83.82,76.2 83.82,81.28 82.55,81.28 RN1.3
N$4  (via drill 0.2 pad 0.7)
  Top 0.375: v90.17,81.28 IC12.9
  Bottom 0.375: RN1.4 85.09,82.23 88.9,82.23 88.9,81.28 v90.17,81.28
N$5  (via drill 0.2 pad 0.7)
  Top 0.375: v87.63,81.28 RN1.5
  Bottom 0.375: IC12.12 82.55,81.28 v87.63,81.28
N$6  (via drill 0.2 pad 0.7)
  Top 0.375: IC13.1 74.93,59.69 v74.93,86.36
  Bottom 0.61: v74.93,86.36 90.17,86.36 RN1.6
N$7  (via drill 0.2 pad 0.7)
  Top 0.375: IC13.4 85.09,62.23 86.36,62.23 v86.36,80.01
  Bottom 0.375: v86.36,80.01 90.17,80.01 91.44,81.28 91.44,83.82 RN1.7
N$8  (via drill 0.2 pad 0.7)
  Top 0.375: v95.25,66.04 RN1.8
  Bottom 0.375: IC13.9 90.17,66.04 v95.25,66.04
N$9  (via drill 0.2 pad 0.7)
  Top 0.375: IC13.12 82.55,69.22 83.82,69.22 v83.82,74.93 | v99.06,74.93 99.06,78.42 97.79,79.69 RN1.9
  Bottom 0.375: v83.82,74.93 v99.06,74.93
N$10  (via drill 0.2 pad 0.7)
  Top 0.375: IC18.2 v26.67,50.8 | v30.48,50.8 30.48,68.58 29.21,68.58 27.94,69.85 v27.94,83.82 | v66.04,83.82 IC10.8
  Bottom 0.375: v26.67,50.8 v30.48,50.8 | v27.94,83.82 50.8,83.82 50.8,85.09 64.14,85.09 64.14,83.82 v66.04,83.82
  Bottom 0.61: v26.67,50.8 v30.48,50.8
N$11
  Top 0.375: IC21.5 IC21.10
  Bottom 0.375: IC21.10 IC21.9 | IC18.8 42.23,55.88 42.23,57.47 53.34,57.47 53.34,58.1 | 53.34,58.1 IC21.2 | IC21.5 60.96,58.1 53.34,58.1
  Bottom 0.61: IC21.10 IC21.9
N$12
  Top 0.375: R2.2 21.59,22.86 15.24,22.86 IC11.4
N$14
  Top 0.375: R16.1 71.12,119.38 D8.A
N$15  (via drill 0.2 pad 0.7)
  Top 0.375: IC8.8 39.37,68.58 40.64,69.85 v40.64,72.39
  Bottom 0.375: v40.64,72.39 41.91,73.66 58.42,73.66 | IC10.4 IC10.5
  Bottom 0.61: IC10.5 IC10.4 58.42,73.66
N$16  (via drill 0.2 pad 0.7)
  Top 0.375: v29.21,53.34 IC18.12 | v46.99,54.61 48.26,55.88 v48.26,68.58
  Bottom 0.375: v29.21,53.34 39.37,53.34 40.64,54.61 v46.99,54.61 | v48.26,68.58 66.04,68.58 IC21.8
N$17
  Top 0.375: IC12.3 82.55,76.2 81.28,76.2 81.28,86.36 78.74,86.36 S1.9
N$18  (via drill 0.2 pad 0.7)
  Top 0.375: IC12.6 90.17,76.2 88.9,76.2 v88.9,87.63 | v81.28,87.63 S1.10
  Bottom 0.375: v88.9,87.63 v81.28,87.63
  Bottom 0.61: v81.28,87.63 v88.9,87.63
N$19
  Top 0.375: IC12.8 92.71,81.28 91.44,82.55 91.44,86.36 90.17,86.36 90.17,88.9 87.63,88.9 87.63,92.71 83.82,92.71 S1.11
N$20
  Top 0.375: IC12.11 85.09,81.28 86.36,81.28 S1.12
N$21  (via drill 0.2 pad 0.7)
  Top 0.375: v76.2,73.66 v76.2,91.44 | v81.28,73.66 81.28,64.77 82.55,64.77 IC13.3
  Bottom 0.254: 88.9,91.44 88.9,91.76 | 87.31,91.76 85.41,91.76 | 84.77,91.76 82.87,91.76 | 82.23,91.76 80.33,91.76 | 79.69,91.76 77.79,91.76
  Bottom 0.375: v81.28,73.66 v76.2,73.66 | S1.13 88.9,91.44
  Bottom 0.61: v81.28,73.66 v76.2,73.66 | S1.13 88.9,91.76 87.31,91.76 | 85.41,91.76 84.77,91.76 | 82.87,91.76 82.23,91.76 | 80.33,91.76 79.69,91.76 | 77.79,91.76 76.52,91.76 v76.2,91.44
N$22  (via drill 0.2 pad 0.7)
  Top 0.375: IC13.6 90.17,64.77 88.9,64.77 v88.9,73.66 | v96.52,73.66 v96.52,87.63 | v91.44,87.63 S1.14
  Bottom 0.375: v88.9,73.66 v96.52,73.66 | v96.52,87.63 v91.44,87.63
  Bottom 0.61: v91.44,87.63 v96.52,87.63 | v88.9,73.66 v96.52,73.66
N$23  (via drill 0.2 pad 0.7)
  Top 0.375: IC13.8 92.71,69.53 91.44,69.53 v91.44,80.01 | v93.98,81.28 S1.15
  Bottom 0.375: v91.44,80.01 92.71,81.28 v93.98,81.28
N$24  (via drill 0.2 pad 0.7)
  Top 0.375: v85.09,63.5 IC13.11 | v99.06,62.23 99.06,71.12 100.33,72.39 100.33,78.74 99.06,80.01 99.06,90.17 S1.16
  Bottom 0.61: v85.09,63.5 85.09,62.23 v99.06,62.23
N$25  (via drill 0.2 pad 0.7)
  Top 0.375: v72.39,97.79 v72.39,101.6 | v12.7,99.06 12.7,88.9 R17.1
  Bottom 0.61: v72.39,101.6 107.95,101.6 107.95,96.52 113.35,96.52 113.35,86.36 110.49,86.36 110.49,55.88 IC19.8 | v72.39,97.79 55.88,97.79 54.61,99.06 14.92,99.06 v12.7,99.06
N$26  (via drill 0.2 pad 0.7)
  Top 0.375: v57.15,82.55 57.15,76.2 60.96,76.2 IC10.10
  Bottom 0.375: IC9.8 47.31,78.74 47.31,81.28 54.61,81.28 55.88,82.55 v57.15,82.55 | IC10.10 IC10.9
  Bottom 0.61: IC10.10 IC10.9
N$27
  Top 0.375: R1.2 19.05,16.51 19.05,21.59 12.7,21.59 IC11.3
N$28  (via drill 0.2 pad 0.7)
  Top 0.375: v11.43,104.14 13.97,104.14 R10.2 | v15.24,64.77 15.24,63.5 16.51,62.23 16.51,27.94 17.78,27.94 IC11.5 | v104.14,111.76 104.14,104.14 100.33,104.14 v100.33,81.28 | v88.9,63.5 88.9,57.78 87.63,57.78 IC19.10
  Bottom 0.375: v88.9,63.5 104.14,63.5 | IC19.10 IC19.9
  Bottom 0.61: v11.43,104.14 20.32,104.14 20.32,107.95 67.95,107.95 69.22,109.22 95.57,109.22 98.11,111.76 v104.14,111.76 | R10.2 8.89,92.71 8.89,91.12 1.91,91.12 1.91,64.77 v15.24,64.77 | v100.33,81.28 104.14,81.28 104.14,63.5 | IC19.10 IC19.9
N$29  (via drill 0.2 pad 0.7)
  Top 0.375: IC11.7 v22.86,17.78
  Bottom 0.375: R3.2 39.05,16.51 37.78,17.78
  Bottom 0.4: 37.78,17.78 37.15,18.42 25.72,18.42 25.08,17.78 v22.86,17.78
N$30  (via drill 0.2 pad 0.7)
  Top 0.375: v25.4,21.59 IC11.8 | v36.83,22.86 v36.83,20.32
  Bottom 0.375: v25.4,21.59 29.53,21.59 29.53,22.86 v36.83,22.86 | v36.83,20.32 R4.2
N$31  (via drill 0.2 pad 0.7)
  Top 0.375: IC11.13 25.4,34.29 26.67,35.56 26.67,46.35 25.4,46.35 v25.4,49.53 | v67.31,49.53 v67.31,29.21 | v74.93,29.21 74.93,16.51 R5.2
  Bottom 0.375: v25.4,49.53 v67.31,49.53 | v67.31,29.21 v74.93,29.21
  Bottom 0.61: v67.31,29.21 v74.93,29.21
N$32  (via drill 0.2 pad 0.7)
  Top 0.375: v63.5,20.32 63.5,26.67 v60.96,26.67 | v19.05,26.67 19.05,27.94 22.86,31.75 IC11.14
  Bottom 0.375: v63.5,20.32 R6.2 | v19.05,26.67 v60.96,26.67
N$33  (via drill 0.2 pad 0.7)
  Top 0.375: v15.24,30.48 IC11.17 | v2.54,30.48 2.54,50.8 3.81,52.07 R7.2
  Bottom 0.375: v2.54,30.48 v15.24,30.48
  Bottom 0.61: v15.24,30.48 v2.54,30.48
N$34
  Top 0.375: IC11.18 12.7,34.29 13.97,35.56 R8.2
N$35  (via drill 0.2 pad 0.7)
  Top 0.375: IC18.9 36.83,58.1 38.1,58.1 v38.1,66.04
  Bottom 0.375: v38.1,66.04 58.42,66.04 IC21.11
N$36
  Top 0.375: R15.1 D7.A
N$37  (via drill 0.2 pad 0.7)
  Top 0.375: v53.34,74.93 IC10.13
  Bottom 0.61: v53.34,74.93 63.5,74.93 IC10.6
N$41
  Top 0.375: R14.1 78.74,119.38 D6.A
N$42
  Top 0.375: R13.1 82.55,119.38 D5.A
N$45  (via drill 0.2 pad 0.7)
  Top 0.375: v38.1,24.13 v38.1,30.48 | v77.47,35.56 IC19.1 | R9.2 93.98,100.65 92.71,100.65 v92.71,86.36 | v93.98,80.01 93.98,46.99 92.71,45.72 v92.71,39.37
  Bottom 0.375: IC11.2 10.16,22.86 28.89,22.86 28.89,24.13 v38.1,24.13 | v38.1,30.48 60.96,30.48 60.96,31.43 63.82,31.43 63.82,35.56 v77.47,35.56 77.47,38.1 91.44,38.1 v92.71,39.37 | IC19.1 IC19.2 | v92.71,86.36 93.98,85.09 96.52,85.09 96.52,82.87
  Bottom 0.61: IC19.1 IC19.2 | 96.52,82.87 96.52,80.01 v93.98,80.01
N$46
  Bottom 0.61: R9.1 96.84,117.16 102.87,117.16 D1.A
N$48
  Top 0.375: R10.1 3.81,96.84 7.62,96.84 7.62,119.38 D2.A
PIN1
  Top 0.375: IC17.1 24.13,104.14 25.4,102.87 25.4,100.33 24.13,99.06 IC16.1 | S3.8 7.62,76.2 6.35,74.93 6.35,72.39 7.62,71.12 S2.8
  Bottom 0.61: IC16.1 24.13,87.63 17.78,87.63 17.78,85.72 7.62,85.72 7.62,85.09 | 7.62,85.09 7.62,84.45 S3.8 | 7.62,85.09 7.62,85.41
PIN3
  Top 0.375: IC17.3 29.21,104.14 30.48,102.87 30.48,100.33 29.21,99.06 IC16.3
  Bottom 0.254: 5.08,79.69 6.67,79.69 8.57,79.69 | 28.26,85.72 26.99,84.45
  Bottom 0.375: 10.16,83.82 S3.7 10.16,79.69
  Bottom 0.61: 8.57,79.69 10.16,79.69 10.16,83.82 26.35,83.82 26.99,84.45 | 6.67,79.69 4.76,79.69 4.76,71.12 10.16,71.12 S2.7 | 28.26,85.72 28.89,86.36 IC16.3
PIN29  (via drill 0.2 pad 0.7)
  Top 0.375: IC17.29 31.75,115.57 30.48,114.3 30.48,104.14 31.75,102.87 IC16.29 31.75,100.33 30.48,99.06 v30.48,82.55 | S3.6 12.7,76.2 11.43,74.93 11.43,72.39 12.7,71.12 S2.6
  Bottom 0.254: 14.29,82.87 16.51,82.87
  Bottom 0.375: S3.6 12.7,82.55
  Bottom 0.61: v30.48,82.55 30.16,82.87 16.51,82.87 | 14.29,82.87 12.7,82.87 S3.6
PIN31  (via drill 0.2 pad 0.7)
  Top 0.375: v15.24,100.33 S3.5 15.24,76.2 13.97,74.93 13.97,72.39 15.24,71.12 S2.5 | IC17.31 26.67,119.38 25.4,118.11 25.4,104.14 26.67,102.87 IC16.31
  Bottom 0.254: 23.18,100.01 25.08,100.01
  Bottom 0.375: IC16.31 26.67,100.33
  Bottom 0.61: v15.24,100.33 15.56,100.01 23.18,100.01 | 25.08,100.01 26.67,100.01 IC16.31
RD  (via drill 0.2 pad 0.7)
  Top 0.375: IC3.16 v17.78,71.12
  Bottom 0.375: IC9.4 IC9.3 IC9.2 IC9.1 v17.78,71.12
  Bottom 0.61: v17.78,71.12 IC9.4
S$1
  Top 0.4: IC4.6 86.36,34.29 IC1.14
S$2
  Bottom 0.61: D4.A 86.36,115.57 R12.1
S$3
  Bottom 0.61: D3.A R11.1
S$5
  Bottom 0.254: 77.79,99.38 79.69,99.38
  Bottom 0.375: S1.7 81.28,99.06
  Bottom 0.61: 79.69,99.38 81.28,99.38 S1.7
VCC  (via drill 0.2 pad 0.7)
  Top 0.375: v7.62,27.94 IC11.20 | v26.67,29.21 v26.67,24.13 | IC2.20 36.83,30.48 35.56,30.48 | 35.56,30.48 C18.2 | C14.2 v44.45,55.88 | v40.64,53.34 40.64,46.35 39.37,46.35 IC5.20 | 35.56,30.48 35.56,41.91 C11.2 | 22.86,101.6 IC16.32 | 22.86,101.6 22.86,120.65 IC17.32 | IC18.14 22.54,55.88 22.54,61.28 24.13,61.28 IC8.14 22.86,67.31 22.86,78.74 | 22.86,78.74 22.86,101.6 | IC9.14 22.86,78.74 | C16.2 66.04,99.06 67.31,100.33 67.31,110.49 C17.2 | v68.58,91.44 68.58,72.39 69.85,72.39 | 69.85,72.39 71.12,73.66 C8.2 | PAD91.1 PAD120.1 92.71,4.13 | 91.76,5.08 v91.44,5.08 | 96.52,41.91 96.52,30.48 | 96.52,41.91 C13.2 | 96.52,30.48 96.52,24.13 | C5.2 96.52,30.48 | C3.2 v66.04,33.02 66.04,34.29 64.77,35.56 64.77,39.37 66.04,39.37 C9.2 | IC1.20 69.85,33.02 69.85,44.45 | 69.85,44.45 69.85,50.8 v71.12,50.8 C7.2 71.12,55.88 69.85,57.15 69.85,60.96 71.12,62.23 C4.2 71.12,67.31 69.85,68.58 69.85,72.39 | 69.85,44.45 IC4.20 | RN1.1 IC12.14 77.47,73.66 76.2,72.39 76.2,67.31 IC13.14 | C19.2 97.79,73.66 96.52,72.39 96.52,69.85 97.79,68.58 C15.2 96.52,63.5 96.52,53.34 | 96.52,53.34 96.52,41.91 | C6.2 96.52,53.34
  Top 1: 92.71,5.08 92.71,21.59 96.52,21.59 96.52,24.13 | 92.71,5.08 92.71,4.13 | 91.76,5.08 92.71,5.08
  Bottom 0.375: v7.62,27.94 7.62,26.99 16.51,26.99 16.51,24.13 v26.67,24.13 | v44.45,55.88 IC7.14 | IC3.20 7.62,42.86 34.29,42.86 | 34.29,42.86 C11.2 | 34.29,42.86 34.29,44.45 | v40.64,53.34 C14.2 58.42,53.34 59.69,52.07 68.58,52.07 69.85,50.8 v71.12,50.8 | v68.58,91.44 C16.2 | PAD91.1 PAD120.1 92.71,5.08 | IC1.20 v66.04,33.02 | C4.2 C10.2 35.56,64.77 | 40.64,68.58 35.56,68.58 35.56,64.77 | 35.56,64.77 24.13,64.77
  Bottom 0.61: C16.2 v68.58,91.44 | C15.2 77.47,64.77 | 77.47,64.77 C4.2 | IC13.14 77.47,64.77 | IC19.14 77.47,53.34 C6.2 | C18.2 30.16,30.48 30.16,29.21 v26.67,29.21 | IC5.20 34.29,44.45 C11.2 | v40.64,53.34 C14.2 | IC8.14 24.13,64.77 C10.2 | C1.2 50.8,76.2 | 50.8,76.2 C8.2 | IC10.14 50.8,76.2 | 40.64,68.58 44.45,68.58 44.45,67.31 IC21.14
  Bottom 0.7: v91.44,5.08 92.71,5.08
VON_374  (via drill 0.2 pad 0.7)
  Top 0.375: IC19.6 90.17,53.34 91.44,53.34 v91.44,68.58 | v59.69,66.04 55.88,66.04 IC21.12
  Bottom 0.375: IC21.13 IC21.12 | v91.44,68.58 69.85,68.58 69.85,66.04 v59.69,66.04
  Bottom 0.61: IC21.13 IC21.12
WR  (via drill 0.2 pad 0.7)
  Top 0.375: v12.7,40.64 IC3.18 | v21.59,40.64 v21.59,59.69 | v86.36,57.15 85.09,57.15 83.82,58.42 v83.82,63.5 | v50.8,63.5 49.53,63.5 v49.53,60.96 | v40.64,63.5 v40.64,60.96 | IC8.4 v31.75,63.5
  Bottom 0.375: v12.7,40.64 v21.59,40.64 | v21.59,59.69 IC8.1 IC8.2 IC8.3 IC8.4 | IC19.13 IC19.12 82.55,57.15 v86.36,57.15 | v50.8,63.5 v83.82,63.5 | v40.64,60.96 v49.53,60.96 | v31.75,63.5 v40.64,63.5
  Bottom 0.61: IC19.13 IC19.12 | v12.7,40.64 v21.59,40.64 | v21.59,59.69 IC8.4 | v31.75,63.5 v40.64,63.5

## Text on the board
Top: 1 | 29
